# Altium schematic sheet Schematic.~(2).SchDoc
size A4; SheetNumber: 1; SheetTotal: 1
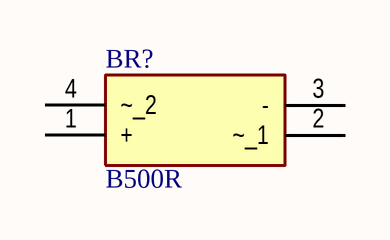
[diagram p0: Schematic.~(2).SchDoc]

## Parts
BR?  B500R  [B500R]

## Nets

Not connected (* = marked no-connect by the designer): BR? 1(+) 2(~_1) 3(-) 4(~_2)

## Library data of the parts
BR? = B500R: Bridge Rectifier; Manufacturer_Name: Diotec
